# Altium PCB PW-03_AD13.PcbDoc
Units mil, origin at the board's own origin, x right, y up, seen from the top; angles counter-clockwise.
Board outline 641.73 x 464.57 mil, 2 copper layers (Top Layer, Bottom Layer); 2 components, 0 nets, 20 pads, 0 vias.
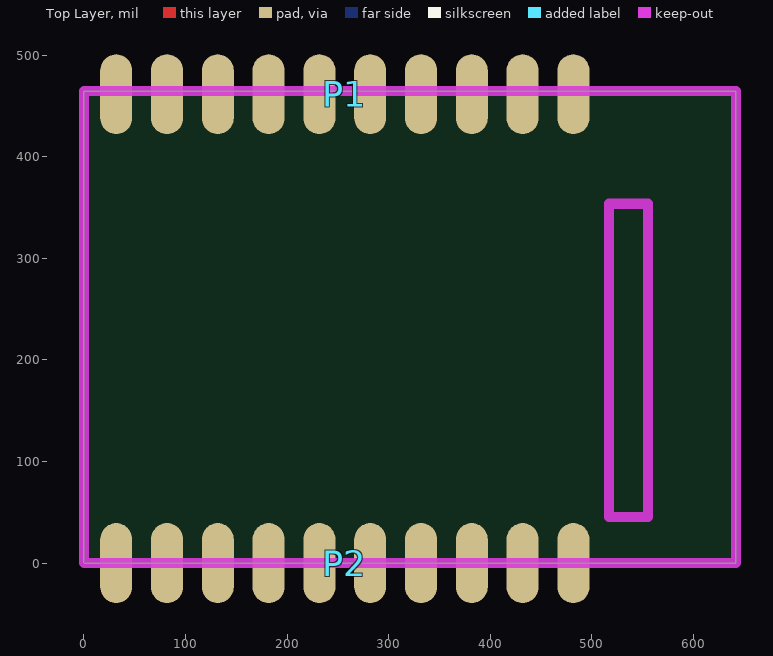
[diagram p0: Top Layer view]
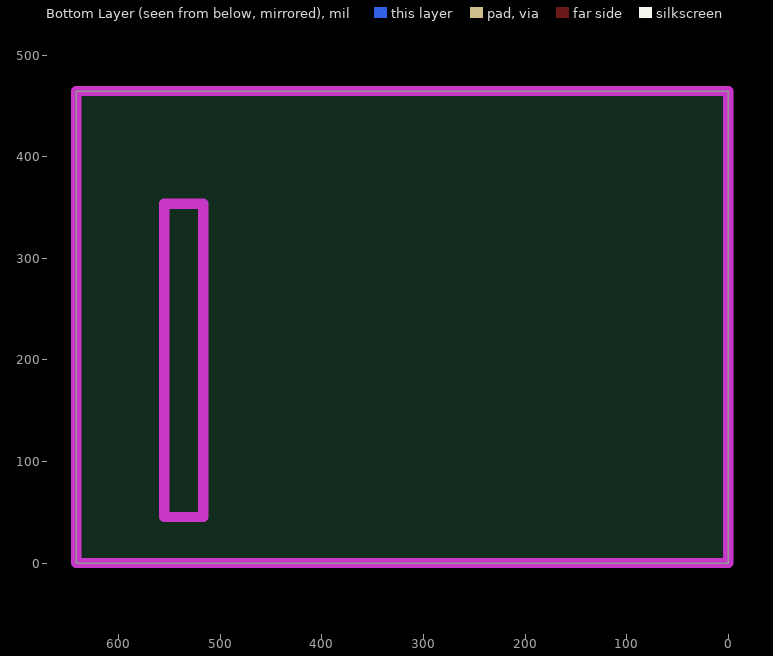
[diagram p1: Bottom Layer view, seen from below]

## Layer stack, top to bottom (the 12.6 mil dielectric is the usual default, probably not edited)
Top Layer: signal copper 1.4
Dielectric: dielectric 12.6, FR-4, Dk 4.8
Bottom Layer: signal copper 1.4

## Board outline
641.73,0 641.73,464.57 0,464.57 0,0

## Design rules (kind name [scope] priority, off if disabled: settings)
Clearance "'Default' PADS rule_18" [All] p1: gap=6
Clearance "'Default' PADS rule_15" [IsVia vs IsVia] p2: gap=6
ComponentClearance "'Default' PADS rule_12" [All] p1: gap=6 collisioncheckmode=3 verticalgap=10 showdistances=FALSE
FlightTimeFalling "'Default' PADS rule_10" [All] p1: maximum=10.00
FlightTimeRising "'Default' PADS rule_9" [All] p1: maximum=10.00
Length "'Default' PADS rule_5" [All] p1: maxlimit=50000 minlimit=0
MatchedLengths "'Default' PADS rule_11" [InNetClass('All Nets')] p1: tolerance=200 checknetsindiffpair=TRUE checkdiffpairvsdiffpair=TRUE checkothers=TRUE
MaxMinImpedance "'Default' PADS rule_8" [All] p1: minimum=50.00 maximum=150.0
ParallelSegment "'Default' PADS rule_7" [All] p1: limit=1000 gap=200
ParallelSegment "'Default' PADS rule_6" [All] p2: limit=1000 gap=200
PlaneClearance "'Default' PADS rule_14" [All] p1: clearance=6
PlaneConnect "Power Plane Connect Style - Via from round thru-hole global defaults" [IsVia] p1: planeconnectstyle=Direct reliefexpansion=20 reliefentries=4 reliefconductorwidth=10 reliefairgap=10
PlaneConnect "Power Plane Connect Style - Round thru-hole pad from global defaults" [IsPad And OnMultiLayer And (PadShape_MidLayer1 = 'Round') And (PadXSize_MidLayer1 = PadYSize_MidLayer1)] p2: planeconnectstyle=Direct reliefexpansion=20 reliefentries=4 reliefconductorwidth=10 reliefairgap=10
PlaneConnect "Power Plane Connect Style - Square thru-hole pad from global defaults" [IsPad And OnMultiLayer And ((PadShape_MidLayer1 = 'Rectangular') Or (PadShape_MidLayer1 = 'Octagonal') Or (PadShape_MidLayer1 = 'Rounded Rectangle')) And (PadXSize_MidLayer1 = PadYSize_MidLayer1)] p3: planeconnectstyle=Direct reliefexpansion=20 reliefentries=4 reliefconductorwidth=10 reliefairgap=10
PlaneConnect "Power Plane Connect Style - Rect thru-hole pad from global defaults" [IsPad And OnMultiLayer And ((PadShape_MidLayer1 = 'Rectangular') Or (PadShape_MidLayer1 = 'Octagonal') Or (PadShape_MidLayer1 = 'Rounded Rectangle')) And (PadXSize_MidLayer1 <> PadYSize_MidLayer1)] p4: planeconnectstyle=Direct reliefexpansion=20 reliefentries=4 reliefconductorwidth=10 reliefairgap=10
PlaneConnect "Power Plane Connect Style - Square-rect thru-hole pad from global defaults" [IsPad And OnMultiLayer And (PadShape_MidLayer1 = 'Rounded Rectangle') And (PadXSize_MidLayer1 = PadYSize_MidLayer1) And (Pad_CornerRadius_MidLayer1 = '0%')] p5: planeconnectstyle=Direct reliefexpansion=20 reliefentries=4 reliefconductorwidth=10 reliefairgap=10
PlaneConnect "Power Plane Connect Style - Oval thru-hole pad from global defaults" [IsPad And OnMultiLayer And (PadShape_MidLayer1 = 'Round') And (PadXSize_MidLayer1 <> PadYSize_MidLayer1)] p6: planeconnectstyle=Direct reliefexpansion=20 reliefentries=4 reliefconductorwidth=10 reliefairgap=10
PlaneConnect "Power Plane Connect Style - Round-oval thru-hole pad from global defaults" [IsPad And OnMultiLayer And (PadShape_MidLayer1 = 'Rounded Rectangle') And (PadXSize_MidLayer1 = PadYSize_MidLayer1) And (Pad_CornerRadius_MidLayer1 = '100%')] p7: planeconnectstyle=Direct reliefexpansion=20 reliefentries=4 reliefconductorwidth=10 reliefairgap=10
PolygonConnect "Polygon Connect Style - Bottom Layer Round SMD from global defaults" [IsSMTPin And (PadShape_BottomLayer = 'Round') And (PadXSize_BottomLayer = PADYSize_BottomLayer) vs Layer = 'Bottom Layer'] p1: connectstyle=Direct reliefconductorwidth=10 reliefentries=4 polygonreliefangle="45 Angle" airgapwidth=10
PolygonConnect "Polygon Connect Style - Top Layer Round SMD from global defaults" [IsSMTPin And (PadShape_TopLayer = 'Round') And (PadXSize_TopLayer = PADYSize_TopLayer) vs Layer = 'Top Layer'] p2: connectstyle=Direct reliefconductorwidth=10 reliefentries=4 polygonreliefangle="45 Angle" airgapwidth=10
PolygonConnect "Polygon Connect Style - Bottom Layer Square SMD from global defaults 1" [IsSMTPin And (PadShape_BottomLayer = 'Rectangular') And (PadXSize_BottomLayer = PADYSize_BottomLayer) vs Layer = 'Bottom Layer'] p3: connectstyle=Direct reliefconductorwidth=10 reliefentries=4 polygonreliefangle="45 Angle" airgapwidth=10
PolygonConnect "Polygon Connect Style - Bottom Layer Square SMD from global defaults 2" [IsSMTPin And (PadShape_BottomLayer = 'Octagonal') And (PadXSize_BottomLayer = PADYSize_BottomLayer) vs Layer = 'Bottom Layer'] p4: connectstyle=Direct reliefconductorwidth=10 reliefentries=4 polygonreliefangle="45 Angle" airgapwidth=10
PolygonConnect "Polygon Connect Style - Bottom Layer Square SMD from global defaults 3" [IsSMTPin And (PadShape_BottomLayer = 'Rounded Rectangle') And (PadXSize_BottomLayer = PADYSize_BottomLayer) vs Layer = 'Bottom Layer'] p5: connectstyle=Direct reliefconductorwidth=10 reliefentries=4 polygonreliefangle="45 Angle" airgapwidth=10
PolygonConnect "Polygon Connect Style - Top Layer Square SMD from global defaults 1" [IsSMTPin And (PadShape_TopLayer = 'Rectangular') And (PadXSize_TopLayer = PADYSize_TopLayer) vs Layer = 'Top Layer'] p6: connectstyle=Direct reliefconductorwidth=10 reliefentries=4 polygonreliefangle="45 Angle" airgapwidth=10
PolygonConnect "Polygon Connect Style - Top Layer Square SMD from global defaults 2" [IsSMTPin And (PadShape_TopLayer = 'Octagonal') And (PadXSize_TopLayer = PADYSize_TopLayer) vs Layer = 'Top Layer'] p7: connectstyle=Direct reliefconductorwidth=10 reliefentries=4 polygonreliefangle="45 Angle" airgapwidth=10
PolygonConnect "Polygon Connect Style - Top Layer Square SMD from global defaults 3" [IsSMTPin And (PadShape_TopLayer = 'Rounded Rectangle') And (PadXSize_TopLayer = PADYSize_TopLayer) vs Layer = 'Top Layer'] p8: connectstyle=Direct reliefconductorwidth=10 reliefentries=4 polygonreliefangle="45 Angle" airgapwidth=10
PolygonConnect "Polygon Connect Style - Bottom Layer Rect SMD from global defaults 1" [IsSMTPin And (PadShape_BottomLayer = 'Rectangular') And (PadXSize_BottomLayer <> PADYSize_BottomLayer) vs Layer = 'Bottom Layer'] p9: connectstyle=Direct reliefconductorwidth=10 reliefentries=4 polygonreliefangle="45 Angle" airgapwidth=10
PolygonConnect "Polygon Connect Style - Bottom Layer Rect SMD from global defaults 2" [IsSMTPin And (PadShape_BottomLayer = 'Octagonal') And (PadXSize_BottomLayer <> PADYSize_BottomLayer) vs Layer = 'Bottom Layer'] p10: connectstyle=Direct reliefconductorwidth=10 reliefentries=4 polygonreliefangle="45 Angle" airgapwidth=10
PolygonConnect "Polygon Connect Style - Bottom Layer Rect SMD from global defaults 3" [IsSMTPin And (PadShape_BottomLayer = 'Rounded Rectangle') And (PadXSize_BottomLayer <> PADYSize_BottomLayer) vs Layer = 'Bottom Layer'] p11: connectstyle=Direct reliefconductorwidth=10 reliefentries=4 polygonreliefangle="45 Angle" airgapwidth=10
PolygonConnect "Polygon Connect Style - Bottom Layer Square-rect SMD pad from global defaults" [IsSMTPin And (PadShape_BottomLayer = 'Rounded Rectangle') And (PadXSize_BottomLayer = PADYSize_BottomLayer) And (Pad_CornerRadius_BottomLayer = '0%') vs Layer = 'Bottom Layer'] p12: connectstyle=Direct reliefconductorwidth=10 reliefentries=4 polygonreliefangle="45 Angle" airgapwidth=10
PolygonConnect "Polygon Connect Style - Top Layer Rect SMD from global defaults 1" [IsSMTPin And (PadShape_TopLayer = 'Rectangular') And (PadXSize_TopLayer <> PADYSize_TopLayer) vs Layer = 'Top Layer'] p13: connectstyle=Direct reliefconductorwidth=10 reliefentries=4 polygonreliefangle="45 Angle" airgapwidth=10
PolygonConnect "Polygon Connect Style - Top Layer Rect SMD from global defaults 2" [IsSMTPin And (PadShape_TopLayer = 'Octagonal') And (PadXSize_TopLayer <> PADYSize_TopLayer) vs Layer = 'Top Layer'] p14: connectstyle=Direct reliefconductorwidth=10 reliefentries=4 polygonreliefangle="45 Angle" airgapwidth=10
PolygonConnect "Polygon Connect Style - Top Layer Rect SMD from global defaults 3" [IsSMTPin And (PadShape_TopLayer = 'Rounded Rectangle') And (PadXSize_TopLayer <> PADYSize_TopLayer) vs Layer = 'Top Layer'] p15: connectstyle=Direct reliefconductorwidth=10 reliefentries=4 polygonreliefangle="45 Angle" airgapwidth=10
PolygonConnect "Polygon Connect Style - Top Layer Square-rect SMD pad from global defaults" [IsSMTPin And (PadShape_TopLayer = 'Rounded Rectangle') And (PadXSize_TopLayer = PADYSize_TopLayer) And (Pad_CornerRadius_TopLayer = '0%') vs Layer = 'Top Layer'] p16: connectstyle=Direct reliefconductorwidth=10 reliefentries=4 polygonreliefangle="45 Angle" airgapwidth=10
PolygonConnect "Polygon Connect Style - Bottom Layer Oval SMD from global defaults" [IsSMTPin And (PadShape_BottomLayer = 'Round') And (PadXSize_BottomLayer <> PADYSize_BottomLayer) vs Layer = 'Bottom Layer'] p17: connectstyle=Direct reliefconductorwidth=10 reliefentries=4 polygonreliefangle="45 Angle" airgapwidth=10
PolygonConnect "Polygon Connect Style - Bottom Layer Round-oval SMD pad from global defaults" [IsSMTPin And (PadShape_BottomLayer = 'Rounded Rectangle') And (PadXSize_BottomLayer = PADYSize_BottomLayer) And (Pad_CornerRadius_BottomLayer = '100%') vs Layer = 'Bottom Layer'] p18: connectstyle=Direct reliefconductorwidth=10 reliefentries=4 polygonreliefangle="45 Angle" airgapwidth=10
PolygonConnect "Polygon Connect Style - Top Layer Oval SMD from global defaults" [IsSMTPin And (PadShape_TopLayer = 'Round') And (PadXSize_TopLayer <> PADYSize_TopLayer) vs Layer = 'Top Layer'] p19: connectstyle=Direct reliefconductorwidth=10 reliefentries=4 polygonreliefangle="45 Angle" airgapwidth=10
PolygonConnect "Polygon Connect Style - Top Layer Round-oval SMD pad from global defaults" [IsSMTPin And (PadShape_TopLayer = 'Rounded Rectangle') And (PadXSize_TopLayer = PADYSize_TopLayer) And (Pad_CornerRadius_TopLayer = '100%') vs Layer = 'Top Layer'] p20: connectstyle=Direct reliefconductorwidth=10 reliefentries=4 polygonreliefangle="45 Angle" airgapwidth=10
PolygonConnect [All] p21: connectstyle=Relief reliefconductorwidth=10 reliefentries=4 polygonreliefangle="90 Angle" airgapwidth=10
RoutingLayers "'Default' PADS rule_3" [All] p1: top layer_v5=FALSE bottom layer_v5=FALSE
RoutingPriority "'Default' PADS rule_2" [All] p1: routingpriority=3
RoutingTopology "'Default' PADS rule" [All] p1: topology=Starburst
RoutingVias "'Default' PADS rule_4" [All] p1: holewidth=12 width=24 viastyle="Through Hole" minholewidth=12 minwidth=24 maxholewidth=12 maxwidth=24
SMDToCorner "'Default' PADS rule_16" [All] p1: distance=60000
SMDToPlane "'Default' PADS rule_17" [All] p1: distance=60000
SolderMaskExpansion [All] p1: expansion=4
Width "'Default' PADS rule_13" [All] p1: maxlimit=120 minlimit=4 preferedwidth=9.84
22 further rules are at their usual default settings.

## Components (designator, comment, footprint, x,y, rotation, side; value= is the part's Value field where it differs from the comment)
P1 "HDR10_1.27A" HDR10_1.27A 481.81,461.5 r180 top
P2 "HDR10_1.27" HDR10_1.27 481.81,0 r180 top

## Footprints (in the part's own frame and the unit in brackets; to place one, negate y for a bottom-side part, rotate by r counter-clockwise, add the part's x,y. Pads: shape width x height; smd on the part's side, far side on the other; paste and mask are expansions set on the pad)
HDR10_1.27 [mm]
  oval 0.8x2 smd: 1(0,0) 2(1.27,0) 3(2.54,0) 4(3.81,0) 5(5.08,0) 6(6.35,0) 7(7.62,0) 8(8.89,0) 9(10.16,0) 10(11.43,0)
HDR10_1.27A [mm]
  oval 0.8x2 smd: 1(0,0) 2(1.27,0) 3(2.54,0) 4(3.81,0) 5(5.08,0) 6(6.35,0) 7(7.62,0) 8(8.89,0) 9(10.16,0) 10(11.43,0)

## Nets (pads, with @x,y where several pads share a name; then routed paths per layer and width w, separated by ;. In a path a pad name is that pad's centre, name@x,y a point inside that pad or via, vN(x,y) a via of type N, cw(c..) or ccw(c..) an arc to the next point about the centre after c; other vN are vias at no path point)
pads on no net: P1.1 P1.2 P1.3 P1.4 P1.5 P1.6 P1.7 P1.8 P1.9 P1.10 P2.1 P2.2 P2.3 P2.4 P2.5 P2.6 P2.7 P2.8 P2.9 P2.10

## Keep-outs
Keep-Out Layer:
  lines w10: 0,0 0,464.57 641.73,464.57 641.73,0 0,0 ; 516.75,45.38 555.12,45.38 555.12,353.75 516.75,353.75 516.75,45.38

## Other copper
Multi-Layer:
  lines w10: -862.2,-4094.33 14897.8,-4094.33 ; 11137.8,-4094.33 11137.8,1745.67

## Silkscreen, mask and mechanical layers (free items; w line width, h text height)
Top:
  pour cut-out: 511.55,458.46 635.43,458.46 635.43,5.17 511.55,5.17 511.55,458.46
  lines w1: 1.26,453.91 1.29,453.91 ; 641.73,464.57 641.76,464.57 ; 641.73,464.57 641.76,464.57 ; 641.73,0 641.76,0
  lines w10: -148.74,555.46 1.26,555.46 ; 1.26,503.91 1.26,605.46 ; 641.73,514.57 641.73,605.46 ; 691.73,0 901.47,0 ; 691.73,464.57 901.47,464.57 ; 791.73,555.46 641.73,555.46 ; 851.47,164.78 851.47,0 ; 851.47,299.78 851.47,464.57 ; 1.26,555.46 -98.74,530.46 -98.74,580.46 1.26,555.46 ; 641.73,555.46 741.73,580.46 741.73,530.46 641.73,555.46 ; 851.47,0 826.47,100 876.47,100 851.47,0 ; 851.47,464.57 876.47,364.57 826.47,364.57 851.47,464.57
  text "16.3mm" at -467.38,517.96 h50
